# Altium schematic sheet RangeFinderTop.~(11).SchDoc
size A; DocumentNumber: 1; SheetNumber: 1; SheetTotal: 6
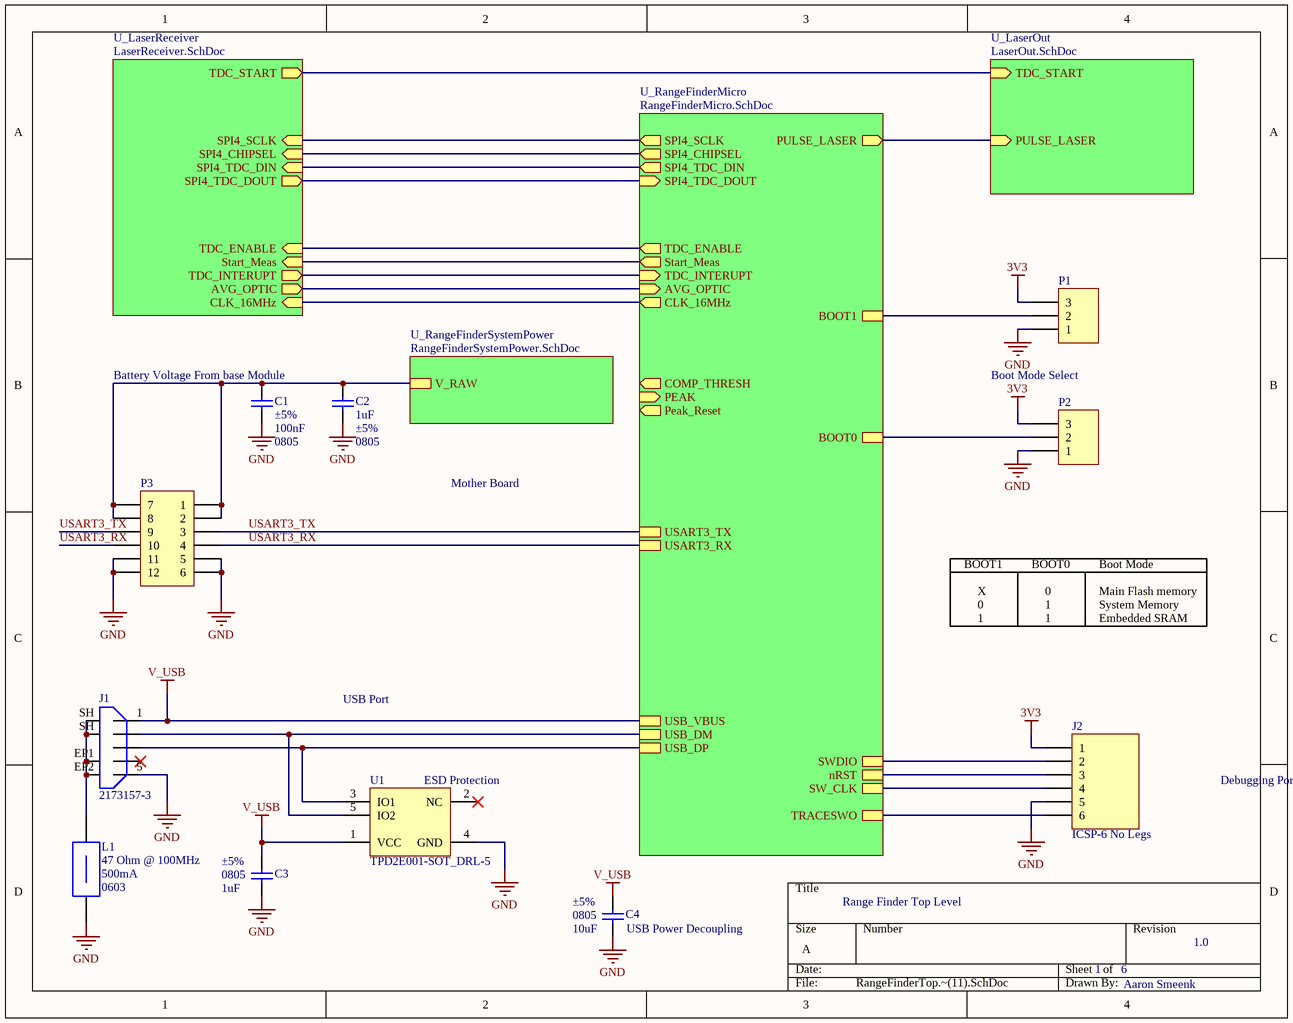
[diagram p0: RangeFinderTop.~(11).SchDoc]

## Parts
C1  value 100nF  Tolerance: ±5%  Case-EIA: 0805  [CAPC0805(2012)100_L]  (hidden comment: CAP 100nF 6.3V 0805(2012))
C2  value 1uF  Tolerance: ±5%  Case-EIA: 0805  [CAPC0805(2012)100_M]  (hidden comment: CAP 1uF 6.3V 0805(2012))
C3  value 1uF  Tolerance: ±5%  Case-EIA: 0805  [CAPC0805(2012)100_M]  (hidden comment: CAP 1uF 6.3V 0805(2012))
C4  value 10uF  Tolerance: ±5%  Case-EIA: 0805  [CAPC0805(2012)100_M]  (hidden comment: CAP 10uF 6.3V 0805(2012))
J1  2173157-3  [2173157-3]
J2  ICSP-6 No Legs  [TC2030-IDC-NL]
L1  Impedance @ Frequency: 47 Ohm @ 100MHz  Current Rating: 500mA  Package / Case: 0603  [LI0603E470R-10]  (hidden comment: LI0603E470R-10)
P1  Header 3  [HDR1X3]  (value not drawn)
P2  Header 3  [HDR1X3]  (value not drawn)
P3  Header 6X2A  [HDR2X6_CEN]  (value not drawn)
U1  TPD2E001-SOT_DRL-5  [TPD2E001DRLR]

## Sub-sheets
U_LaserOut = LaserOut.SchDoc: PULSE_LASER (in), TDC_START (in)
U_LaserReceiver = LaserReceiver.SchDoc: Start_Meas (in), TDC_ENABLE (in), SPI4_SCLK (in), SPI4_CHIPSEL (in), SPI4_TDC_DIN (in), SPI4_TDC_DOUT (out), TDC_INTERUPT (out), AVG_OPTIC (out), CLK_16MHz (in), TDC_START (out)
U_RangeFinderMicro = RangeFinderMicro.SchDoc: USART3_TX, USART3_RX, SWDIO, SW_CLK, TRACESWO, BOOT1, BOOT0, USB_DP, USB_DM, USB_VBUS, nRST, SPI4_SCLK (out), SPI4_TDC_DOUT (in), SPI4_CHIPSEL (out), SPI4_TDC_DIN (out), Start_Meas (out), TDC_ENABLE (out), TDC_INTERUPT (in), AVG_OPTIC (in), PULSE_LASER (out), CLK_16MHz (out), COMP_THRESH (out), PEAK (in), Peak_Reset (out)
U_RangeFinderSystemPower = RangeFinderSystemPower.SchDoc: V_RAW

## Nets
3V3: J2.1 P1.3 P2.3
GND: C1.1 C2.1 C3.1 C4.1 J1.5(GND) J2.5 L1.1 P1.1 P2.1 P3.5 P3.6 P3.11 P3.12 U1.4(GND)
V_USB: C3.2 C4.2 J1.1(5V) U1.1(VCC) ; sheet U_RangeFinderMicro/USB_VBUS
USART3_RX: P3.4 P3.10 ; sheet U_RangeFinderMicro/USART3_RX
USART3_TX: P3.3 P3.9 ; sheet U_RangeFinderMicro/USART3_TX
NetC1_2: C1.2 C2.2 P3.1 P3.2 P3.7 P3.8 ; sheet U_RangeFinderSystemPower/V_RAW
NetJ1_2: J1.2(D-) U1.5(IO2) ; sheet U_RangeFinderMicro/USB_DM
NetJ1_3: J1.3(D+) U1.3(IO1) ; sheet U_RangeFinderMicro/USB_DP
NetJ1_EP1: J1.EP1 J1.EP2 J1.SH L1.2
NetJ2_2: J2.2 ; sheet U_RangeFinderMicro/SWDIO
NetJ2_3: J2.3 ; sheet U_RangeFinderMicro/nRST
NetJ2_4: J2.4 ; sheet U_RangeFinderMicro/SW_CLK
NetJ2_6: J2.6 ; sheet U_RangeFinderMicro/TRACESWO
NetP1_2: P1.2 ; sheet U_RangeFinderMicro/BOOT1
NetP2_2: P2.2 ; sheet U_RangeFinderMicro/BOOT0
(unnamed): sheet U_LaserOut/PULSE_LASER, sheet U_RangeFinderMicro/PULSE_LASER
(unnamed): sheet U_LaserOut/TDC_START, sheet U_LaserReceiver/TDC_START  [a separate net that carries the same name]
(unnamed): sheet U_LaserReceiver/Start_Meas, sheet U_RangeFinderMicro/Start_Meas  [a separate net that carries the same name]
(unnamed): sheet U_LaserReceiver/TDC_ENABLE, sheet U_RangeFinderMicro/TDC_ENABLE  [a separate net that carries the same name]
(unnamed): sheet U_LaserReceiver/SPI4_SCLK, sheet U_RangeFinderMicro/SPI4_SCLK  [a separate net that carries the same name]
(unnamed): sheet U_LaserReceiver/SPI4_CHIPSEL, sheet U_RangeFinderMicro/SPI4_CHIPSEL  [a separate net that carries the same name]
(unnamed): sheet U_LaserReceiver/SPI4_TDC_DIN, sheet U_RangeFinderMicro/SPI4_TDC_DIN  [a separate net that carries the same name]
(unnamed): sheet U_LaserReceiver/SPI4_TDC_DOUT, sheet U_RangeFinderMicro/SPI4_TDC_DOUT  [a separate net that carries the same name]
(unnamed): sheet U_LaserReceiver/TDC_INTERUPT, sheet U_RangeFinderMicro/TDC_INTERUPT  [a separate net that carries the same name]
(unnamed): sheet U_LaserReceiver/AVG_OPTIC, sheet U_RangeFinderMicro/AVG_OPTIC  [a separate net that carries the same name]
(unnamed): sheet U_LaserReceiver/CLK_16MHz, sheet U_RangeFinderMicro/CLK_16MHz  [a separate net that carries the same name]

Not connected (* = marked no-connect by the designer): J1 4(ID)*; U1 2(NC)*

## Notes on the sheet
- (near C1) Battery Voltage From base Module
- Boot Mode Select
- Mother Board
- BOOT1
- BOOT0
- Boot Mode
- X
- 0
- 1
- Main Flash memory
- System Memory
- Embedded SRAM
- USB Port
- (near U1) ESD Protection
- Debugging Port
- Range Finder Top Level
- (near C4) USB Power Decoupling
- 6
- 1.0
- Aaron Smeenk

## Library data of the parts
C1 = CMP-1036-04390-1: CAP 100nF 6.3V ±5% 0805 (2012 Metric) Thickness 1mm SMD; Case-Metric: 2012
C2 C3 = CMP-1036-04730-1: CAP 1uF 6.3V ±5% 0805 (2012 Metric) Thickness 1mm SMD; Case-Metric: 2012
C4 = CMP-1036-04730-1: CAP 10uF 6.3V ±5% 0805 (2012 Metric) Thickness 1mm SMD; Case-Metric: 2012
J1 = 2173157-3: USB Connectors SPLASH PROOF MICRO 5P USB B-TYPE; Number of Ports: 1; Number of Contacts: 5; Gender: Female; Brand: TE Connectivity; Mounting Angle: Right
J2 = ICSP-6 No Legs: 6 Pin Connector
L1 = LI0603E470R-10: FERRITE CHIP 47 OHMS 500MA 0603; DC Resistance (DCR): 100 mOhm Max; Filter Type: Differential Mode - Single
P1 P2 = Header 3: Header, 3-Pin
P3 = Header 6X2A: Header, 6-Pin, Dual row
U1 = TPD2E001DRLR: TVS DIODE 5.5VWM 100VC SOT5; Bidirectional Channels: 2; Voltage - Reverse Standoff (Typ): 5.5V (Max); Voltage - Breakdown (Min): 11V; Voltage - Clamping (Max) @ Ipp: 100V; Power Line Protection: Yes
